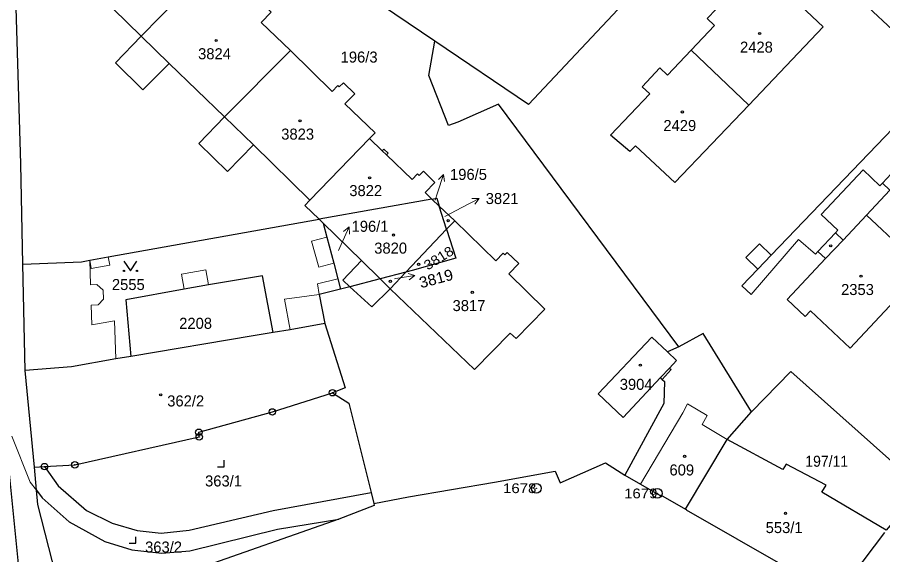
# Model space of a CAD drawing. Extents: x -679733 to -673243, y -1075091 to -1066557.
# Drawn here: x -676561.2 to -676427.8, y -1071191.3 to -1071108.5 of the extents above; entities that cross this region are included whole.
import ezdxf
from ezdxf.enums import TextEntityAlignment as Align

# ---------------------------------------------------------------- set-up
doc = ezdxf.new("R2010")
doc.units = 0
doc.header["$LTSCALE"] = 0.68
for name, color, linetype, lineweight in [('1', 7, 'Continuous', 25), ('3', 7, 'Continuous', 25), ('4', 7, 'Continuous', 13), ('5', 7, 'Continuous', 25), ('7', 7, 'Continuous', 13), ('8', 7, 'Continuous', 25)]:
    doc.layers.add(name, color=color, linetype=linetype, lineweight=lineweight)
doc.layers.add('2', color=7, linetype='Continuous')

msp = doc.modelspace()

# ---------------------------------------------------------------- linework, layer by layer
at = {"layer": '1'}
for p, q in [((-676531.96, -1071101.03), (-676542.05, -1071111.37)), ((-676519.07, -1071113.59), (-676529.23, -1071123.82)), ((-676457.34, -1071113.56), (-676448.43, -1071121.99)), ((-676506.88, -1071127.15), (-676516.07, -1071136.64)), ((-676514.02, -1071140.21), (-676514.66, -1071139.59)), ((-676430.33, -1071138.94), (-676421.42, -1071147.29)), ((-676501.28, -1071147.76), (-676503.69, -1071150.29)), ((-676558.5, -1071177.8), (-676556.98, -1071177.71)), ((-676427.54, -1071187.85), (-676434.92, -1071197.55))]:
    msp.add_line(p, q, dxfattribs=at)
for points in [[(-676566.43, -1070961.91), (-676569.23, -1071023.51), (-676569.31, -1071051.96), (-676567.07, -1071105.14), (-676564.66, -1071149.4), (-676563.82, -1071164.93), (-676560.23, -1071200.41), (-676554.07, -1071198.82)], [(-676560.3, -1071146.5), (-676560.63, -1071131.04), (-676561.44, -1071103.53), (-676561.64, -1071096.36), (-676561.94, -1071087.67), (-676561.7, -1071087.65), (-676561.93, -1071081.5), (-676562.1, -1071081.5), (-676562.67, -1071060.48), (-676562.54, -1071060.48), (-676562.52, -1071055.56), (-676562.05, -1071055.53), (-676562.5, -1071049.32), (-676562.68, -1071049.33), (-676563.11, -1071042.56), (-676562.77, -1071037.79), (-676568.16, -1071037.22), (-676567.55, -1071023.82)], [(-676496.82, -1071112.13), (-676515.29, -1071099.61), (-676523.78, -1071093.92), (-676524.52, -1071084.32), (-676509.8, -1071083.17), (-676507.74, -1071058.94)], [(-676441.05, -1071077.89), (-676482.39, -1071121.91), (-676496.82, -1071112.13)], [(-676542.05, -1071111.37), (-676550.74, -1071102.84), (-676546.98, -1071098.96), (-676548.74, -1071096.92), (-676548.73, -1071096.62)], [(-676531.96, -1071101.03), (-676525.59, -1071107.23), (-676524.75, -1071106.36), (-676524.45, -1071106.66), (-676523.8, -1071105.99), (-676522.05, -1071107.69), (-676523.57, -1071109.27), (-676519.07, -1071113.59)], [(-676457.34, -1071113.56), (-676453.72, -1071109.75), (-676454.88, -1071108.65), (-676452.11, -1071105.73), (-676450.95, -1071106.84), (-676445.02, -1071100.6), (-676442.2, -1071103.29), (-676443.06, -1071104.2), (-676436.99, -1071109.95), (-676448.43, -1071121.99)], [(-676529.23, -1071123.82), (-676537.74, -1071115.57), (-676541.8, -1071119.63), (-676546.01, -1071115.49), (-676542.05, -1071111.37)], [(-676459.21, -1071159.23), (-676486.99, -1071121.84), (-676493.29, -1071124.61), (-676494.73, -1071125.17), (-676497.74, -1071117.46), (-676496.82, -1071112.13)], [(-676519.07, -1071113.59), (-676512.66, -1071119.9), (-676511.78, -1071118.98), (-676511.54, -1071119.2), (-676510.9, -1071118.56), (-676509.15, -1071120.25), (-676510.67, -1071121.82), (-676506.02, -1071126.3), (-676506.88, -1071127.15)], [(-676448.43, -1071121.99), (-676459.86, -1071133.93), (-676465.92, -1071128.27), (-676466.78, -1071129.17), (-676469.77, -1071126.65), (-676463.72, -1071120.28), (-676464.88, -1071119.17), (-676462.13, -1071116.26), (-676460.95, -1071117.37), (-676457.34, -1071113.56)], [(-676516.07, -1071136.64), (-676524.78, -1071128.14), (-676528.76, -1071132.25), (-676533.19, -1071127.93), (-676529.23, -1071123.82)], [(-676430.33, -1071138.94), (-676426.69, -1071135.11), (-676427.86, -1071134.02), (-676425.19, -1071131.16), (-676424.04, -1071132.23), (-676418.14, -1071125.93), (-676415.34, -1071128.54), (-676416.17, -1071129.42), (-676410.04, -1071135.15), (-676421.42, -1071147.29)], [(-676506.88, -1071127.15), (-676504.92, -1071129.03), (-676504.68, -1071128.78), (-676504.03, -1071129.41), (-676504.27, -1071129.66), (-676500.32, -1071133.47), (-676499.49, -1071132.61), (-676499.23, -1071132.86), (-676498.59, -1071132.2), (-676496.8, -1071133.91), (-676498.33, -1071135.47), (-676497.28, -1071136.48)], [(-676514.66, -1071139.59), (-676516.86, -1071137.45), (-676516.07, -1071136.64)], [(-676495, -1071141.14), (-676496.14, -1071137.57), (-676497.28, -1071136.48), (-676514.66, -1071139.59)], [(-676497.28, -1071136.48), (-676496.53, -1071136.35), (-676496.14, -1071137.57), (-676493.76, -1071139.83)], [(-676560.3, -1071146.5), (-676551.28, -1071146.13), (-676550, -1071145.9), (-676547.15, -1071145.39), (-676514.66, -1071139.59)], [(-676509.91, -1071149.99), (-676511.01, -1071148.97), (-676508.11, -1071145.95), (-676514.02, -1071140.21)], [(-676514.02, -1071140.21), (-676513.46, -1071142.33), (-676512.4, -1071146.37), (-676511.77, -1071148.76), (-676511.35, -1071150.36)], [(-676493.76, -1071139.83), (-676487.42, -1071146), (-676486.27, -1071144.82), (-676486.02, -1071145.07), (-676485.68, -1071144.73), (-676483.87, -1071146.42), (-676485.42, -1071147.98), (-676479.87, -1071153.46), (-676484.28, -1071157.98), (-676485.21, -1071157.14), (-676490.72, -1071162.75), (-676503.69, -1071150.29)], [(-676493.76, -1071139.83), (-676495, -1071141.14), (-676501.28, -1071147.76)], [(-676421.42, -1071147.29), (-676432.81, -1071159.44), (-676438.93, -1071153.7), (-676439.76, -1071154.58), (-676442.54, -1071151.97), (-676436.65, -1071145.66), (-676437.8, -1071144.58), (-676435.1, -1071141.68), (-676433.89, -1071142.81), (-676430.33, -1071138.94)], [(-676495, -1071141.14), (-676493.58, -1071145.61), (-676500.32, -1071147.51), (-676501.28, -1071147.76)], [(-676554.07, -1071198.82), (-676557.99, -1071183.56), (-676558.19, -1071181.33), (-676558.5, -1071177.8), (-676559.94, -1071162.91), (-676560.3, -1071146.5)], [(-676501.28, -1071147.76), (-676505.23, -1071148.78), (-676509.91, -1071149.99)], [(-676521.74, -1071157.05), (-676523.35, -1071148.29), (-676531.72, -1071149.7), (-676535.47, -1071150.37), (-676544.44, -1071151.99), (-676543.66, -1071160.73)], [(-676511.35, -1071150.36), (-676514.62, -1071151.21), (-676513.78, -1071155.66)], [(-676503.69, -1071150.29), (-676506.55, -1071153.09), (-676509.91, -1071149.99), (-676511.35, -1071150.36)], [(-676513.78, -1071155.66), (-676519.13, -1071156.61), (-676521.74, -1071157.05)], [(-676513.78, -1071155.66), (-676512.87, -1071158.56), (-676510.64, -1071165.56), (-676512.59, -1071166.32)], [(-676521.74, -1071157.05), (-676524.82, -1071157.55), (-676543.66, -1071160.73)], [(-676448.02, -1071169.28), (-676455.46, -1071157.18), (-676459.21, -1071159.23), (-676460.99, -1071160.04), (-676459.59, -1071161.36)], [(-676461.78, -1071164.26), (-676462.03, -1071163.99), (-676467.81, -1071170.12), (-676471.64, -1071166.5), (-676463.37, -1071157.78), (-676460.99, -1071160.04)], [(-676543.66, -1071160.73), (-676545.96, -1071161.11), (-676552.82, -1071162.34), (-676559.94, -1071162.91)], [(-676459.59, -1071161.36), (-676460.67, -1071162.52), (-676460.43, -1071162.75), (-676461.78, -1071164.26)], [(-676448.02, -1071169.28), (-676441.97, -1071163.06), (-676424.06, -1071179.05), (-676421.27, -1071181.38), (-676425.72, -1071185.7), (-676427.27, -1071187.49)], [(-676461.78, -1071164.26), (-676461.41, -1071164.59), (-676461.52, -1071167.97), (-676467.55, -1071179.04)], [(-676556.98, -1071177.71), (-676552.29, -1071177.43), (-676533.12, -1071173.14), (-676533.18, -1071172.42), (-676521.86, -1071169.28), (-676512.59, -1071166.32)], [(-676512.59, -1071166.32), (-676510.06, -1071167.91), (-676506.65, -1071181.7), (-676506.23, -1071183.38)], [(-676467.55, -1071179.04), (-676465.13, -1071180.42), (-676462.12, -1071182.15), (-676462.07, -1071182.06), (-676458.2, -1071184.24), (-676451.79, -1071173.55), (-676448.02, -1071169.28)], [(-676427.27, -1071187.49), (-676437.17, -1071181.66), (-676436.52, -1071180.56), (-676442.7, -1071177.34), (-676443.21, -1071178.14), (-676451.79, -1071173.55)], [(-676506.23, -1071183.38), (-676500.88, -1071182.36), (-676487.62, -1071180.1), (-676478.29, -1071178.43), (-676477.49, -1071180.21), (-676470.53, -1071177.1), (-676467.55, -1071179.04)], [(-676556.98, -1071177.71), (-676554.87, -1071180.69), (-676550.48, -1071184.46), (-676546.53, -1071186.41), (-676542.67, -1071187.53), (-676538.98, -1071187.95), (-676534.66, -1071187.51), (-676521.74, -1071184.45), (-676506.65, -1071181.7)], [(-676558.19, -1071181.33), (-676557.32, -1071182.53), (-676553.14, -1071186.2), (-676547.69, -1071189.23), (-676543.52, -1071190.51), (-676538.9, -1071191.02), (-676534.55, -1071190.69), (-676521.07, -1071187.33), (-676511.59, -1071185.79)], [(-676506.23, -1071183.38), (-676506.16, -1071183.68), (-676511.59, -1071185.79)], [(-676434.92, -1071197.55), (-676434.98, -1071197.63), (-676458.06, -1071184.44), (-676458.01, -1071184.35), (-676458.2, -1071184.24)], [(-676511.59, -1071185.79), (-676533.86, -1071193.61), (-676554.07, -1071198.82)]]:
    msp.add_lwpolyline(points, dxfattribs=at)
at = {"layer": '3'}
for points in [[(-676544.73, -1071146.049), (-676543.73, -1071147.55), (-676542.73, -1071146.049)], [(-676530.301, -1071177.73), (-676529.3, -1071177.73), (-676529.3, -1071176.73)], [(-676543.911, -1071189.51), (-676542.91, -1071189.51), (-676542.91, -1071188.51)]]:
    msp.add_lwpolyline(points, dxfattribs=at)
for centre in [(-676544.73, -1071147.5495), (-676542.73, -1071147.5495)]:
    msp.add_circle(centre, 0.1, dxfattribs=at)
at = {"layer": '4'}
for p, q in [((-676445.04, -1071092.81), (-676418.61, -1071117.63)), ((-676542.05, -1071111.37), (-676537.74, -1071115.57)), ((-676529.23, -1071123.82), (-676524.78, -1071128.14)), ((-676445, -1071145.12), (-676424.99, -1071124.28)), ((-676504.92, -1071129.03), (-676504.27, -1071129.66)), ((-676430.81, -1071131.98), (-676437.3, -1071138.84)), ((-676428.24, -1071134.42), (-676430.81, -1071131.98)), ((-676427.86, -1071134.02), (-676428.24, -1071134.42)), ((-676437.3, -1071138.84), (-676434.72, -1071141.28)), ((-676434.72, -1071141.28), (-676435.1, -1071141.68)), ((-676515.84, -1071142.95), (-676513.46, -1071142.33)), ((-676440.8, -1071142.72), (-676448.1, -1071151.21)), ((-676438.15, -1071144.99), (-676440.8, -1071142.72)), ((-676436.65, -1071145.66), (-676433.89, -1071142.81)), ((-676515.84, -1071142.95), (-676514.71, -1071146.98)), ((-676448.88, -1071145.51), (-676446.82, -1071143.37)), ((-676446.82, -1071143.37), (-676445, -1071145.12)), ((-676546.92, -1071146.67), (-676547.15, -1071145.39)), ((-676447.06, -1071147.26), (-676448.88, -1071145.51)), ((-676445, -1071145.12), (-676447.06, -1071147.26)), ((-676437.8, -1071144.58), (-676438.15, -1071144.99)), ((-676550, -1071145.9), (-676549.77, -1071147.18)), ((-676549.88, -1071149.69), (-676550, -1071145.9)), ((-676549.77, -1071147.18), (-676546.92, -1071146.67)), ((-676514.71, -1071146.98), (-676512.4, -1071146.37)), ((-676508.11, -1071145.95), (-676505.23, -1071148.78)), ((-676535.84, -1071148.03), (-676532.13, -1071147.38)), ((-676535.47, -1071150.37), (-676535.84, -1071148.03)), ((-676532.13, -1071147.38), (-676531.72, -1071149.7)), ((-676449.53, -1071149.84), (-676447.06, -1071147.26)), ((-676514.9, -1071149.55), (-676511.77, -1071148.76)), ((-676514.62, -1071151.21), (-676514.9, -1071149.55)), ((-676505.23, -1071148.78), (-676503.69, -1071150.29)), ((-676548.88, -1071149.66), (-676549.88, -1071149.69)), ((-676547.91, -1071150.5), (-676548.88, -1071149.66)), ((-676547.86, -1071151.93), (-676547.91, -1071150.5)), ((-676448.1, -1071151.21), (-676449.53, -1071149.84)), ((-676548.68, -1071152.78), (-676547.86, -1071151.93)), ((-676514.62, -1071151.21), (-676520, -1071151.91)), ((-676520, -1071151.91), (-676519.13, -1071156.61)), ((-676549.78, -1071152.81), (-676548.68, -1071152.78)), ((-676549.69, -1071155.86), (-676549.78, -1071152.81)), ((-676546.19, -1071155.27), (-676549.69, -1071155.86)), ((-676545.96, -1071161.11), (-676546.19, -1071155.27)), ((-676462.03, -1071163.99), (-676460.67, -1071162.52)), ((-676458.61, -1071169.42), (-676457.89, -1071168.03)), ((-676457.89, -1071168.03), (-676454.87, -1071169.85)), ((-676465.13, -1071180.42), (-676458.61, -1071169.42)), ((-676454.87, -1071169.85), (-676455.64, -1071171.21)), ((-676455.64, -1071171.21), (-676451.79, -1071173.55)), ((-676559.18, -1071180.11), (-676562.01, -1071173.01)), ((-676558.19, -1071181.33), (-676559.18, -1071180.11))]:
    msp.add_line(p, q, dxfattribs=at)
at = {"layer": '5'}
for centre in [(-676446.7868, -1071110.9692), (-676530.5168, -1071112.0492), (-676458.6768, -1071123.0592), (-676517.5968, -1071124.4292), (-676506.8768, -1071133.2092), (-676494.7668, -1071139.8192), (-676503.1868, -1071142.0392), (-676435.8268, -1071143.6892), (-676499.3168, -1071146.5492), (-676431.1368, -1071148.3592), (-676503.6768, -1071149.1492), (-676491.0468, -1071150.8392), (-676465.1468, -1071162.0792), (-676539.0568, -1071166.6492), (-676458.3468, -1071176.1392), (-676442.7868, -1071184.9192)]:
    msp.add_circle(centre, 0.175, dxfattribs=at)
at = {"layer": '7'}
for p, q in [((-676495.483, -1071132.676), (-676496.268, -1071133.474)), ((-676489.99, -1071136.381), (-676491.11, -1071136.409)), ((-676510.039, -1071140.748), (-676510.904, -1071141.46)), ((-676499.886, -1071148.271), (-676500.953, -1071147.933))]:
    msp.add_line(p, q, dxfattribs=at)
for points in [[(-676496.77, -1071136.65), (-676496.41, -1071135.53), (-676495.483, -1071132.676), (-676495.316, -1071133.783)], [(-676495.26, -1071139.16), (-676492.64, -1071137.79), (-676489.99, -1071136.381), (-676490.639, -1071137.293)], [(-676511.65, -1071144.39), (-676511.26, -1071143.49), (-676510.039, -1071140.748), (-676509.989, -1071141.867)], [(-676503.06, -1071148.78), (-676502.85, -1071148.74), (-676499.886, -1071148.271), (-676500.797, -1071148.922)]]:
    msp.add_lwpolyline(points, dxfattribs=at)
at = {"layer": '8'}
for centre, radius in [((-676512.59, -1071166.3199), 0.5), ((-676512.59, -1071166.3199), 0.0303), ((-676521.86, -1071169.2799), 0.5), ((-676521.86, -1071169.2799), 0.0303), ((-676533.18, -1071172.4199), 0.5), ((-676533.12, -1071173.1399), 0.5), ((-676533.18, -1071172.4199), 0.0303), ((-676533.12, -1071173.1399), 0.0303), ((-676556.98, -1071177.7099), 0.5), ((-676552.29, -1071177.4299), 0.5), ((-676552.29, -1071177.4299), 0.0303), ((-676556.98, -1071177.7099), 0.0303), ((-676481.18, -1071181.0398), 0.75), ((-676481.18, -1071181.0398), 0.03), ((-676462.53, -1071181.8398), 0.75), ((-676462.53, -1071181.8398), 0.03)]:
    msp.add_circle(centre, radius, dxfattribs=at)

# ---------------------------------------------------------------- texts
at = {"layer": '2'}
for s, p in [('2428', (-676447.27, -1071113.92)), ('3824', (-676530.77, -1071114.94)), ('196/3', (-676508.49, -1071115.45)), ('2429', (-676459.08, -1071125.999)), ('3823', (-676517.96, -1071127.32)), ('3822', (-676507.47, -1071136.029)), ('3820', (-676503.63, -1071144.89)), ('2555', (-676544.05, -1071150.499)), ('2353', (-676431.7, -1071151.269)), ('3817', (-676491.56, -1071153.749)), ('2208', (-676533.68, -1071156.479)), ('3904', (-676465.8, -1071165.88)), ('362/2', (-676535.21, -1071168.44)), ('609', (-676458.769, -1071179.07)), ('363/1', (-676529.38, -1071180.769)), ('553/1', (-676443, -1071187.95)), ('363/2', (-676538.62, -1071190.95))]:
    msp.add_text(s, height=1.7, dxfattribs=at).set_placement(p, align=Align.CENTER)
for s, p in [('196/5', (-676494.48, -1071133.529)), ('3821', (-676488.98, -1071137.249)), ('196/1', (-676509.65, -1071141.529))]:
    msp.add_text(s, height=1.7, dxfattribs=at).set_placement(p)
at = {"layer": '2', "width": 1.1}
msp.add_text('3818', height=1.5, rotation=32, dxfattribs=at).set_placement((-676495.8369, -1071146.2101), align=Align.CENTER)
at = {"layer": '2', "width": 1.05}
msp.add_text('3819', height=1.7, rotation=15, dxfattribs=at).set_placement((-676498.97, -1071150.241))
at = {"layer": '2', "width": 0.95}
msp.add_text('197/11', height=1.7, dxfattribs=at).set_placement((-676436.439, -1071177.729), align=Align.CENTER)
at = {"layer": '8', "width": 1.15}
for s, p in [('1678', (-676481.179, -1071181.79)), ('1679', (-676462.529, -1071182.59))]:
    msp.add_text(s, height=1.5, dxfattribs=at).set_placement(p, align=Align.RIGHT)

doc.saveas('drawing.dxf')
